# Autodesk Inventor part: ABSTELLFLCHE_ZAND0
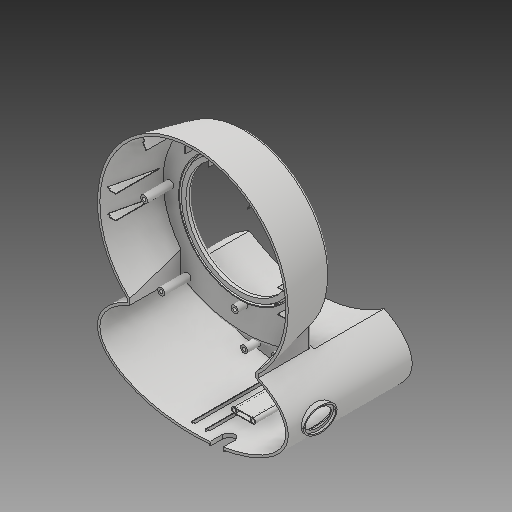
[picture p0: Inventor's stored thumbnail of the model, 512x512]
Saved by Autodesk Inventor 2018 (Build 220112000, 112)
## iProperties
Created: 2019-01
Part Number: ABSTELLFLCHE_ZAND0
Material: Polypropylene (PP)
Document SubType Name: Modeling
Designer: zand
Density: 0.902188 g/cm^3
Appearance: Vorgabe
Mass: 118.296 g
Surface Area: 1526.85 cm^2
Volume: 131.121 cm^3
Author: zand
Revision Number: 32LAST_VERSION
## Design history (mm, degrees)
feature "Basis1"
node "Volumenkörper1"
